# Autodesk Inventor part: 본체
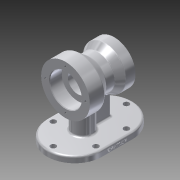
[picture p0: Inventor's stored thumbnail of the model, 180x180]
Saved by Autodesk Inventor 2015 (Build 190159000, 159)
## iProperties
Created: 2020-01
Part Number: 본체
Material: 알루미늄 6061
Document SubType Name: Modeling
Designer: LINEART-SSD.D4.16.05
Density: 2.7 g/cm^3
Appearance: 알루미늄 - 평지
Mass: 911.053 g
Surface Area: 638.133 cm^2
Volume: 337.427 cm^3
Author: LINEART-SSD.D4.16.05
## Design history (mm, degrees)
sketch "스케치1"
  geometry: L1 (-45, 25)-(-45, -25); L2 (45, -25)-(45, 25); L3 (0, 25)-(0, 0); L4 (0, 0)-(0, -25); A1 r 45 centre (0, 25) between (45, 25) and (-45, 25); A2 r 45 centre (0, -25) between (-45, -25) and (45, -25)
  constraints: 8 end point, 4 point on circle, 4 tangent, 2 centre point, 2 equal length, 2 vertical alignment, 1 collinear, 1 vertical
  dimensions: "d4" = 45 radius of A1; "d5" = 50 distance of L4.end L3.start
extrude "돌출1" new body sketch "스케치1" distance "d6" = 10; taper "d7" = 0 deg
sketch "스케치2"
  geometry: L1 (5, 3.199)-(5, 30); L2 (5, 30)-(-5, 30); L3 (-5, 30)-(-5, 3.199); A1 r 45 centre (0, -25) between (-45, -25) and (45, -25) reference; A2 r 16 centre (0, -12) between (-5, 3.199) and (5, 3.199); A3 r 45 centre (0, 25) between (45, 25) and (-45, 25) reference; 2 further points
  constraints: 6 end point, 2 point on circle, 2 vertical alignment, 1 centre point, 1 horizontal, 1 midpoint, 1 parallel, 1 vertical
  dimensions: "d8" = 16 radius of A2; "d9" = 13 distance of A1.centre A2.centre; "d10" = 10 distance of L1.end L2.end; "d88" = 5 distance from line of A3.centre L2
extrude "돌출2" join sketch "스케치2" distance "d12" = 70; taper "d13" = 0 deg
node "작업 평면2"
  node "작업 평면1"
sketch "스케치7"
  geometry: L1 (3.199, 80)-(-28, 80) reference; L2 (-70, 0)-(-70, 10) reference; L3 (-40, 80)-(-40, 120); L4 (-40, 120)-(-16, 120); L5 (-16, 120)-(-1.103, 107.5); L6 (-1.103, 107.5)-(13.289, 107.5); L7 (13.289, 107.5)-(24, 115); L8 (24, 115)-(40, 115); L9 (40, 115)-(40, 80); L10 (-40, 80)-(40, 80); L11 (-65, 80)-(72.993, 80); L12 (30, 10)-(30, 80) reference; 3 further points
  constraints: 18 end point, 2 horizontal, 2 horizontal alignment, 2 midpoint, 2 parallel, 2 perpendicular, 1 vertical
  dimensions: "d23" = 80 diameter of L4 L11; "d25" = 55 diameter of L6 L11; "d26" = 24 distance of L3.end L4.end; "d27" = 16 distance of L7.end L8.end; "d28" = 70 diameter of L8 L11; "d30" = 40 deg angle of L6 L5; "d31" = 35 deg angle of L7 L6; "d86" = 80 distance between parallel lines of L3 L9; "d87" = 30 distance between parallel lines of L2 L3; "d89" = 10 distance between parallel lines of L12 L9 (derived)
revolve "회전1" sketch "스케치7" stored, may be unused: angle "d32" = 90 deg
sketch "스케치8"
  geometry: C1 r 40 at (0, 0) reference; C2 r 26 at (0, 0); 1 further point
  constraints: 1 centre point, 1 coincident
  dimensions: "d33" = 52 diameter of C2
extrude "돌출5" cut sketch "스케치8" distance "d34" = 20; taper "d35" = 0 deg
sketch "스케치9"
  geometry: C1 r 35 at (0, 0) reference; C2 r 20 at (0, 0); 1 further point
  constraints: 1 centre point, 1 coincident
  dimensions: "d36" = 40 diameter of C2
extrude "돌출6" cut sketch "스케치9" distance "d37" = 17; taper "d38" = 0 deg
sketch "스케치10"
  geometry: C1 r 20 at (0, 0) reference; C2 r 16 at (0, 0); 1 further point
  constraints: 1 centre point, 1 coincident
  dimensions: "d39" = 32 diameter of C2
extrude "돌출7" cut sketch "스케치10" stored distance "d40" = 17; taper "d41" = 0 deg
sketch "스케치11" dims "d42" = 66
  geometry: C1 r 40 at (0, 0) reference; 6 further points
  constraints: 2 vertical alignment, 1 coincident, 7 other
  dimensions: "d45" = 360 deg dimension on C1.centre point (0, 33) (derived)
hole "구멍1" sketch "스케치11" at (0, 33), (-33, 0), (0, -33), (33, 0) diameter "d47" = 3.242; stored, may be unused: countersink angle "d51" = 90 deg, drill point angle "d53" = 118 deg; dims "d48" = 9, "d49" = 4, "d50" = 2, "d52" = 11
sketch "스케치12" dims "d54" = 55
  geometry: C1 r 35 at (0, 0) reference; 6 further points
  constraints: 2 vertical alignment, 1 coincident, 7 other
  dimensions: "d57" = 360 deg dimension on C1.centre point (0, -27.5) (derived)
hole "구멍2" sketch "스케치12" at (0, -27.5), (27.5, 0), (0, 27.5), (-27.5, 0) diameter "d59" = 3.242; stored, may be unused: countersink angle "d63" = 90 deg, drill point angle "d65" = 118 deg; dims "d60" = 9, "d61" = 4, "d62" = 2, "d64" = 11
sketch "스케치13"
  geometry: L1 (0, -25)-(0, 25); L2 (35, -25)-(35, 25); L3 (-35, 25)-(-35, -25); L4 (45, -25)-(45, 25) reference; A1 r 45 centre (0, 25) between (45, 25) and (-45, 25) reference; A2 r 45 centre (0, -25) between (-45, -25) and (45, -25) reference; A3 r 35 centre (0, -25) between (-35, -25) and (35, -25); A4 r 35 centre (0, 25) between (35, 25) and (-35, 25); 7 further points
  constraints: 8 end point, 6 point on circle, 4 coincident, 4 tangent, 2 centre point, 1 midpoint, 1 parallel, 1 vertical
  dimensions: "d66" = 10 distance between parallel lines of L4 L2
hole "구멍3" sketch "스케치13" at (0, 60), (0, -60), (-35, -25), (-35, 25), (35, 25), (35, -25) diameter "d67" = 9; stored, may be unused: countersink angle "d71" = 90 deg, drill point angle "d73" = 0 deg; dims "d68" = 9, "d69" = 4, "d70" = 2, "d72" = 11
fillet "모깎기1" dims "d74" = 0.3
chamfer "모따기1" distance "d75" = 1; stored, may be unused: second distance "d76" = 2, angle "d77" = 45 deg
chamfer "모따기2" distance "d78" = 1; stored, may be unused: second distance "d79" = 2, angle "d80" = 45 deg
fillet "모깎기2" dims "d81" = 3
sketch "스케치14"
  geometry: L1 (0, 0)-(0, 50) reference; L2 (0, -45)-(-7, -45) reference; 2 further points
  constraints: 1 other
  dimensions: "d82" = 4 distance from line of L1 point (-4, 25); "d83" = 70 distance from line of L2 point (-4, 25)
feature "엠보싱1" sketch "스케치14" dims "d4" = 45, "d5" = 50, "d84" = 0.5, "d85" = 0
node "솔리드1"
